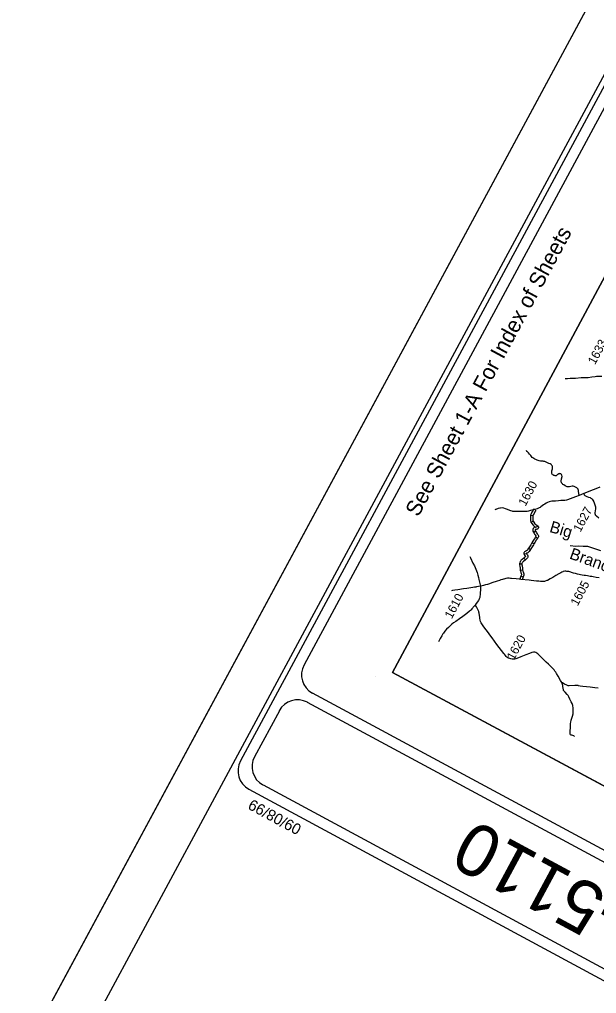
# Model space of a CAD drawing. Extents: x 1376167 to 1379209, y 761324 to 763997.
# Drawn here: x 1376166.9 to 1376443.7, y 762547.7 to 763014.5 of the extents above; entities that cross this region are included whole.
import ezdxf

# ---------------------------------------------------------------- set-up
doc = ezdxf.new("R2010")
doc.units = 0
for name, color, linetype in [('Default', 7, 'Continuous'), ('Old_Level_1', 7, 'Continuous'), ('Sheet Border Standard 30in CELL', 7, 'Continuous'), ('Sheet Cutting Line CELL', 7, 'Continuous'), ('Sheet Plot Border Inside CELL', 7, 'Continuous'), ('Sheet Plot Border Outside CELL', 7, 'Continuous'), ('Sheet Title CELL', 7, 'Continuous')]:
    doc.layers.add(name, color=color, linetype=linetype)

msp = doc.modelspace()

# ---------------------------------------------------------------- linework, layer by layer
at = {"layer": 'Default'}
for p, q in [((1376437.56, 762787.25), (1376435.36, 762786.42)), ((1376415.13, 762779.97), (1376414.13, 762779.68)), ((1376412.06, 762776.99), (1376413.16, 762776.71)), ((1376412.2, 762773.65), (1376413.22, 762774.14)), ((1376413.43, 762768.72), (1376414.4, 762769.29)), ((1376414.35, 762771.2), (1376415.72, 762771.59)), ((1376414.47, 762766.52), (1376415.41, 762765.92)), ((1376411.03, 762761.1), (1376411.98, 762760.49)), ((1376412.74, 762763.79), (1376413.69, 762763.19)), ((1376408.8, 762756.33), (1376409.53, 762755.48)), ((1376408.82, 762758.44), (1376409.97, 762758.55)), ((1376406.74, 762753.66), (1376407.88, 762753.61)), ((1376407.1, 762750.44), (1376408.21, 762750.68)), ((1376407.42, 762747.71), (1376408.48, 762747.33))]:
    msp.add_line(p, q, dxfattribs=at)
for points in [[(1376428.65, 762842.47), (1376429.73, 762842.51), (1376431.08, 762842.55), (1376432.73, 762842.67), (1376433.63, 762842.64), (1376436.24, 762842.87), (1376437.65, 762842.9), (1376439.73, 762842.96), (1376441.45, 762843.2), (1376442.95, 762843.46), (1376443.59, 762843.53), (1376444.38, 762843.56), (1376445.29, 762843.61), (1376446.28, 762843.59)], [(1376422.31, 762796.97), (1376422.22, 762797.4), (1376422.18, 762797.8), (1376422.23, 762798.12), (1376422.4, 762798.64), (1376422.56, 762799.07), (1376422.6, 762799.25), (1376422.63, 762799.59), (1376422.61, 762800), (1376422.49, 762800.42), (1376422.28, 762800.81), (1376422.11, 762801.03), (1376421.88, 762801.23), (1376421.44, 762801.49), (1376420.84, 762801.75), (1376420.22, 762802.03), (1376419.77, 762802.21), (1376418.81, 762802.6), (1376418.4, 762802.74), (1376418.14, 762802.82), (1376417.96, 762802.8), (1376417.37, 762802.76), (1376417.05, 762802.77), (1376416.72, 762802.82), (1376416.1, 762803.02), (1376415.24, 762803.38), (1376414.92, 762803.51), (1376414.12, 762803.81), (1376413.54, 762804.07), (1376413.08, 762804.39), (1376412.86, 762804.61), (1376412.53, 762805.05), (1376412.13, 762805.52), (1376411.58, 762806.16), (1376410.97, 762806.84), (1376410.51, 762807.27), (1376410.32, 762807.5), (1376410.09, 762807.86)], [(1376435.36, 762786.42), (1376435.05, 762788.41), (1376434.98, 762788.79), (1376434.89, 762789.18), (1376434.81, 762789.44), (1376434.55, 762789.79), (1376434.26, 762790.01), (1376433.87, 762790.25), (1376433.28, 762790.59), (1376432.88, 762790.75), (1376432.52, 762790.83), (1376432.22, 762790.81), (1376431.98, 762790.79), (1376430.71, 762790.6), (1376430.22, 762790.49), (1376429.53, 762790.56), (1376429.3, 762790.64), (1376428.69, 762790.99), (1376427.93, 762791.4), (1376427.53, 762791.69), (1376427.27, 762792.01), (1376426.94, 762792.45), (1376426.86, 762792.64), (1376426.75, 762792.88), (1376426.72, 762793.2), (1376426.91, 762794.32), (1376427.11, 762795.53), (1376427.01, 762796.15), (1376426.84, 762796.48), (1376426.61, 762796.7), (1376426.37, 762796.8), (1376426.13, 762796.85), (1376425.9, 762796.83), (1376425.62, 762796.76), (1376425.12, 762796.48), (1376424.83, 762796.28), (1376424.51, 762795.91), (1376424.3, 762795.78), (1376424.09, 762795.76), (1376423.88, 762795.81), (1376423.57, 762795.88), (1376423.34, 762795.92), (1376423.11, 762796.01), (1376422.69, 762796.22), (1376422.58, 762796.34), (1376422.41, 762796.57), (1376422.31, 762796.97)], [(1376445.31, 762790.3), (1376443.4, 762789.59), (1376442.12, 762789.08), (1376441.58, 762788.85), (1376439.64, 762788.09), (1376437.56, 762787.25)], [(1376435.36, 762786.42), (1376433.53, 762785.74), (1376429.79, 762784.21), (1376429.26, 762784.1), (1376428.51, 762784.03), (1376427.45, 762783.98), (1376426.54, 762783.9), (1376425.42, 762783.79), (1376424.01, 762783.7), (1376423.26, 762783.67), (1376422.6, 762783.62), (1376422.25, 762783.58), (1376421.02, 762783.3), (1376420.2, 762783.02), (1376419.45, 762782.63), (1376418.83, 762782.28), (1376418.26, 762781.89), (1376417.61, 762781.4), (1376417.01, 762780.97), (1376416.66, 762780.69), (1376416.12, 762780.38), (1376415.13, 762779.97)], [(1376437.56, 762787.25), (1376437.81, 762786.74), (1376438.09, 762786.44), (1376438.43, 762786.26), (1376439.07, 762785.95), (1376439.87, 762785.58), (1376440.55, 762785.39), (1376440.99, 762785.15), (1376441.3, 762784.93), (1376441.61, 762784.59), (1376441.93, 762784.12), (1376442.34, 762783.3), (1376443.04, 762781.43), (1376443.12, 762780.9), (1376443.17, 762780.52), (1376443.16, 762779.96), (1376443.03, 762779.01), (1376442.9, 762778.01), (1376442.87, 762777.65), (1376442.97, 762777.37), (1376443.09, 762777.12), (1376443.33, 762776.84), (1376443.62, 762776.57), (1376444.84, 762775.72)], [(1376409.99, 762778.75), (1376409.31, 762778.65), (1376408.82, 762778.67), (1376407.7, 762778.67), (1376406.5, 762778.68), (1376405.84, 762778.67), (1376405.3, 762778.7), (1376404.13, 762778.67), (1376403.48, 762778.77), (1376403.19, 762778.83), (1376402.56, 762779.07), (1376400.53, 762779.84), (1376399.97, 762780.02), (1376399.23, 762780.22), (1376398.4, 762780.38), (1376397.57, 762780.37), (1376397.27, 762780.3), (1376396.5, 762780.08), (1376395.43, 762779.7), (1376395.14, 762779.59), (1376394.85, 762779.44)], [(1376413.64, 762779.95), (1376413.3, 762779.35), (1376412.7, 762778.36), (1376412.28, 762777.55), (1376412.06, 762776.99), (1376411.97, 762776.36), (1376411.97, 762775.58), (1376411.95, 762774.93), (1376411.96, 762774.33), (1376412.2, 762773.65), (1376412.67, 762772.89), (1376413.29, 762772.11), (1376413.77, 762771.65), (1376414.35, 762771.2), (1376414.03, 762771.13), (1376413.69, 762771.01), (1376413.43, 762770.76), (1376413.23, 762770.47), (1376413.09, 762770.13), (1376413.07, 762769.65), (1376413.09, 762769.54), (1376413.17, 762769.22), (1376413.43, 762768.72), (1376413.72, 762768.27), (1376413.96, 762767.86), (1376414.26, 762767.45), (1376414.48, 762767.07), (1376414.62, 762766.79), (1376414.55, 762766.64), (1376414.47, 762766.52), (1376414.17, 762766.04), (1376413.82, 762765.49), (1376413.19, 762764.46), (1376412.87, 762763.97), (1376412.44, 762763.31), (1376412.12, 762762.76), (1376411.52, 762761.83), (1376410.73, 762760.62), (1376410.49, 762760.24), (1376410.2, 762759.93), (1376410.12, 762759.89), (1376409.96, 762759.8), (1376409.67, 762759.68), (1376409.4, 762759.54), (1376409.18, 762759.37), (1376408.97, 762759.12), (1376408.87, 762758.81), (1376408.82, 762758.44), (1376408.91, 762758.07), (1376409.18, 762757.71), (1376409.49, 762757.36), (1376409.56, 762757.28), (1376409.61, 762757.16), (1376409.61, 762757.15), (1376409.6, 762757.12), (1376409.48, 762757), (1376409.16, 762756.66), (1376408.8, 762756.33), (1376407.98, 762755.66), (1376407.56, 762755.3), (1376407.3, 762755.01), (1376407.05, 762754.69), (1376406.82, 762754.14), (1376406.74, 762753.66), (1376406.79, 762753.07), (1376406.87, 762752.44), (1376406.95, 762752.1), (1376406.98, 762751.96), (1376407, 762751.42), (1376407.1, 762750.44), (1376407.32, 762749.77), (1376407.42, 762749.5), (1376407.55, 762748.99), (1376407.63, 762748.71), (1376407.63, 762748.44), (1376407.64, 762748.36), (1376407.42, 762747.71), (1376406.88, 762746.33)], [(1376414.62, 762779.41), (1376414.27, 762778.78), (1376413.68, 762777.81), (1376413.31, 762777.09), (1376413.16, 762776.71), (1376413.1, 762776.28), (1376413.1, 762775.56), (1376413.08, 762774.91), (1376413.08, 762774.53), (1376413.22, 762774.14), (1376413.59, 762773.54), (1376414.13, 762772.86), (1376414.51, 762772.5), (1376415.03, 762772.09), (1376415.72, 762771.59), (1376415.77, 762771.25), (1376415.8, 762770.98), (1376415.64, 762770.5), (1376415.28, 762770.27), (1376415.03, 762770.19), (1376414.68, 762770.12), (1376414.34, 762770.04), (1376414.29, 762770.03), (1376414.23, 762769.94), (1376414.21, 762769.88), (1376414.2, 762769.76), (1376414.23, 762769.62), (1376414.4, 762769.29), (1376414.68, 762768.86), (1376414.9, 762768.48), (1376415.2, 762768.07), (1376415.47, 762767.6), (1376415.78, 762766.96), (1376415.77, 762766.56), (1376415.62, 762766.29), (1376415.53, 762766.08), (1376415.41, 762765.92), (1376415.12, 762765.44), (1376414.77, 762764.89), (1376414.14, 762763.87), (1376413.82, 762763.35), (1376413.39, 762762.72), (1376413.08, 762762.18), (1376412.47, 762761.22), (1376411.68, 762760.02), (1376411.38, 762759.54), (1376410.91, 762759.06), (1376410.69, 762758.91), (1376410.45, 762758.78), (1376410.15, 762758.66), (1376410.01, 762758.58), (1376409.97, 762758.55), (1376409.97, 762758.54), (1376410.05, 762758.43), (1376410.35, 762758.09), (1376410.53, 762757.87), (1376410.71, 762757.46), (1376410.75, 762757.09), (1376410.68, 762756.78), (1376410.53, 762756.46), (1376410.28, 762756.22), (1376409.95, 762755.86), (1376409.53, 762755.48), (1376408.7, 762754.8), (1376408.36, 762754.5), (1376408.17, 762754.29), (1376408.02, 762754.11), (1376407.91, 762753.84), (1376407.88, 762753.61), (1376407.91, 762753.19), (1376407.98, 762752.64), (1376408.06, 762752.32), (1376408.1, 762752.08), (1376408.12, 762751.5), (1376408.21, 762750.68), (1376408.39, 762750.14), (1376408.5, 762749.84), (1376408.63, 762749.29), (1376408.76, 762748.88), (1376408.76, 762748.45), (1376408.76, 762748.19), (1376408.48, 762747.33), (1376407.93, 762745.92)], [(1376414.13, 762779.68), (1376412.65, 762779.26), (1376411.96, 762779.1), (1376411.05, 762778.85), (1376410.41, 762778.75), (1376409.99, 762778.75)], [(1376445.76, 762759.78), (1376439.49, 762761.92), (1376437.21, 762761.91), (1376434.8, 762762.02), (1376433.67, 762761.93), (1376430.95, 762762.28)], [(1376382.87, 762757.09), (1376383.21, 762756.46), (1376384.32, 762754.01), (1376385.16, 762752.58), (1376385.83, 762751.07), (1376386.17, 762750.27), (1376386.42, 762749.51), (1376386.79, 762748.19), (1376387.04, 762747.09), (1376387.24, 762746.06), (1376387.72, 762744.26), (1376387.96, 762742.89)], [(1376407.4, 762746.12), (1376406.55, 762746.2), (1376405.14, 762746.42), (1376402.94, 762746.58), (1376402.37, 762746.64), (1376401.71, 762746.67), (1376401.02, 762746.67), (1376400.38, 762746.63), (1376400.15, 762746.56), (1376399.74, 762746.46), (1376399.19, 762746.32), (1376399.03, 762746.28), (1376398.51, 762746.15), (1376397.77, 762745.88), (1376397.11, 762745.66), (1376395.99, 762745.32), (1376393.52, 762744.5), (1376392.27, 762744.08), (1376391.32, 762743.76), (1376390.4, 762743.49), (1376389.54, 762743.22), (1376388.82, 762743.02), (1376387.96, 762742.89)], [(1376444.89, 762746.96), (1376443.56, 762747.14), (1376442.11, 762747.35), (1376441.41, 762747.49), (1376440.6, 762747.6), (1376439.39, 762747.8), (1376438.3, 762748), (1376437.75, 762748.08), (1376436.82, 762748.2), (1376436.02, 762748.36), (1376435.33, 762748.47), (1376434.53, 762748.69), (1376433.54, 762748.94), (1376432.55, 762749.21), (1376430.38, 762749.94), (1376429.47, 762750.01), (1376428.96, 762750.06), (1376428.51, 762750.05), (1376427.71, 762749.9), (1376427.44, 762749.8), (1376427.01, 762749.64), (1376426.51, 762749.34), (1376425.57, 762748.79), (1376424.15, 762747.99), (1376422.66, 762747.11), (1376421.38, 762746.37), (1376420.12, 762745.66), (1376419.8, 762745.56), (1376419.04, 762745.25), (1376418.7, 762745.18), (1376418.29, 762745.14), (1376417.49, 762745.12), (1376416.75, 762745.19), (1376415.94, 762745.24), (1376414.91, 762745.35), (1376413.65, 762745.48), (1376412.35, 762745.6), (1376411.3, 762745.72), (1376407.4, 762746.12)], [(1376387.96, 762742.89), (1376387.05, 762742.75), (1376386.05, 762742.57), (1376385.71, 762742.5), (1376385.22, 762742.41), (1376384.27, 762742.29), (1376381.39, 762741.81), (1376379.89, 762741.61), (1376377.22, 762741.19), (1376375.73, 762740.98), (1376374.64, 762740.82), (1376374.1, 762740.73)], [(1376387.96, 762742.89), (1376387.99, 762741.2), (1376387.91, 762739.74), (1376387.83, 762738.85), (1376387.73, 762738.02), (1376387.64, 762737.5), (1376387.55, 762737.16), (1376387.39, 762736.78), (1376387.2, 762736.37), (1376387.04, 762736.11), (1376386.35, 762735.18), (1376386.1, 762734.82), (1376385.91, 762734.6), (1376385.4, 762733.87)], [(1376385.4, 762733.87), (1376384.87, 762733.22), (1376384.58, 762732.83), (1376384.31, 762732.47), (1376383.9, 762732.03), (1376383.52, 762731.6), (1376383.19, 762731.25), (1376382.8, 762730.86), (1376381.52, 762729.83), (1376379.48, 762728.33), (1376378.02, 762727.28), (1376376.19, 762726.04), (1376375.15, 762725.31), (1376374.29, 762724.66), (1376373.76, 762724.2), (1376373.3, 762723.73), (1376372.61, 762723.04), (1376371.79, 762722.24), (1376370.93, 762721.28), (1376370.23, 762720.31), (1376370.03, 762720.02), (1376369.44, 762719.15), (1376368.66, 762717.83), (1376368.3, 762717.19), (1376368, 762716.61), (1376367.82, 762716.17)], [(1376400.32, 762709.21), (1376399.97, 762709.61), (1376399.49, 762710.24), (1376399.19, 762710.61), (1376395.92, 762714.99), (1376393.55, 762718.15), (1376392.95, 762718.97), (1376392.15, 762720.09), (1376391.31, 762721.23), (1376390.69, 762722.05), (1376389.65, 762723.37), (1376388.94, 762724.34), (1376388.59, 762724.83), (1376388.35, 762725.31), (1376388.08, 762725.92), (1376387.83, 762726.69), (1376387.7, 762727.55), (1376387.68, 762727.85), (1376387.38, 762729.98), (1376387.28, 762730.4), (1376387.2, 762730.75), (1376387.03, 762731.12), (1376386.46, 762732.3), (1376386.08, 762732.97), (1376385.62, 762733.61), (1376385.4, 762733.87)], [(1376427.05, 762696.66), (1376426.44, 762697.63), (1376425.22, 762699.76), (1376424.51, 762701.02), (1376424.09, 762701.71), (1376423.72, 762702.21), (1376423.3, 762702.81), (1376421.48, 762704.7), (1376420.66, 762705.48), (1376419.55, 762706.56), (1376417.94, 762708.11), (1376416.99, 762709.03), (1376415.45, 762710.51), (1376414.98, 762710.85), (1376414.59, 762711.06), (1376414.04, 762711.22), (1376413.69, 762711.26), (1376413.41, 762711.24), (1376412.65, 762711.06), (1376411.57, 762710.66), (1376409.81, 762709.92), (1376407.38, 762709), (1376406.24, 762708.55), (1376405.01, 762708.13), (1376404.37, 762707.95), (1376403.84, 762707.91), (1376403.19, 762707.93), (1376402.61, 762708.03), (1376402.01, 762708.19), (1376401.41, 762708.46), (1376400.73, 762708.86), (1376400.32, 762709.21)], [(1376444.38, 762693.98), (1376442.88, 762694.11), (1376441.79, 762694.33), (1376440.61, 762694.56), (1376437.02, 762694.86), (1376435.85, 762695.02), (1376435.04, 762695.17), (1376434.81, 762695.24), (1376434.13, 762695.33), (1376433.34, 762695.32), (1376430.49, 762695.16), (1376430.04, 762695.21), (1376429.71, 762695.29), (1376429.4, 762695.42), (1376428.31, 762695.99), (1376427.39, 762696.52), (1376427.05, 762696.66)], [(1376433.09, 762670.92), (1376432.76, 762671.17), (1376432.32, 762671.4), (1376431.86, 762671.46), (1376431.68, 762671.51), (1376431.46, 762671.56), (1376431.21, 762671.72), (1376431.08, 762671.93), (1376431.04, 762672.24), (1376431.07, 762673.35), (1376431.15, 762675.18), (1376431.19, 762676.39), (1376431.21, 762677.11), (1376431.28, 762677.69), (1376431.52, 762678.69), (1376431.68, 762679.17), (1376432.1, 762680.55), (1376432.39, 762681.7), (1376432.44, 762682.38), (1376432.43, 762683.68), (1376432.42, 762684.75), (1376432.37, 762685.43), (1376432.31, 762685.75), (1376432.15, 762686.2), (1376431.96, 762686.71), (1376431.56, 762687.49), (1376430.93, 762688.68), (1376430.41, 762689.81), (1376430.03, 762690.5), (1376429.65, 762691), (1376428.6, 762692.1), (1376428.15, 762692.59), (1376427.9, 762692.94), (1376427.8, 762693.24), (1376427.67, 762694.03), (1376427.56, 762694.83), (1376427.45, 762695.38), (1376427.05, 762696.66)]]:
    msp.add_lwpolyline(points, dxfattribs=at)
at = {"layer": 'Old_Level_1'}
for points in [[(1376622.61, 762553.05), (1376345.79, 762701.47), (1376550.88, 763083.99), (1376827.7, 762935.57)], [(1376345.79, 762701.47), (1376660.36, 762532.81), (1376865.45, 762915.33), (1376550.88, 763083.99)]]:
    msp.add_lwpolyline(points, close=True, dxfattribs=at)
at = {"layer": 'Sheet Border Standard 30in CELL'}
msp.add_line((1376337.75, 762699.38), (1376337.75, 762699.38), dxfattribs=at)
at = {"layer": 'Sheet Cutting Line CELL'}
msp.add_line((1376166.94, 762515.18), (1376966.07, 763997.49), dxfattribs=at)
at = {"layer": 'Sheet Plot Border Inside CELL'}
msp.add_lwpolyline([(1377121.6, 762015.28), (1377912.43, 763482.18), (1376983.7, 763982.88), (1376192.87, 762515.97)], close=True, dxfattribs=at)
at = {"layer": 'Sheet Plot Border Outside CELL'}
msp.add_lwpolyline([(1376966.07, 763997.49), (1376166.94, 762515.18), (1377135.18, 761993.19), (1377934.31, 763475.5)], close=True, dxfattribs=at)
at = {"layer": 'Sheet Title CELL'}
for p, q in [((1377042.48, 762295.37), (1376307.48, 762691.62)), ((1377202.95, 762203.18), (1376305.11, 762687.22))]:
    msp.add_line(p, q, dxfattribs=at)
for points in [[(1376975.27, 763961.87), (1376272.92, 762659.12)], [(1376977.29, 763955.09), (1376303.44, 762705.17)], [(1376291.57, 762683.15), (1376279.7, 762661.15)], [(1376283.76, 762647.62), (1377181.59, 762163.57)], [(1376276.98, 762645.58), (1377183.62, 762156.8)], [(1376276.98, 762645.58), (1377183.62, 762156.8)]]:
    msp.add_lwpolyline(points, dxfattribs=at)
for centre, start, end in [((1376312.19, 762700.45), 151.6702, 241.6702), ((1376300.33, 762678.44), 61.6702, 151.6702), ((1376281.69, 762654.41), 151.6702, 241.6702), ((1376288.46, 762656.43), 151.6702, 241.6702)]:
    msp.add_arc(centre, 10, start, end, dxfattribs=at)

# ---------------------------------------------------------------- texts
at = {"layer": 'Default'}
for s, rotation, p in [('Big', 343.4163, (1376420.76, 762768.99)), ('Branch', 340.1164, (1376430.32, 762756.25))]:
    msp.add_text(s, height=5.58, rotation=rotation, dxfattribs=at).set_placement(p)
at = {"layer": 'Old_Level_1'}
for s, p in [('1633', (1376442.92, 762848.77)), ('1630', (1376409.59, 762780.92)), ('1627', (1376435.92, 762768.5)), ('1605', (1376434.6, 762733.11)), ('1610', (1376374.22, 762726.95)), ('1620', (1376404.05, 762707.12))]:
    msp.add_text(s, height=4.185, rotation=61.8015, dxfattribs=at).set_placement(p)
at = {"layer": 'Sheet Title CELL'}
for s, height, rotation, p in [('See Sheet 1-A For Index of Sheets', 7.5, 61.6702, (1376358.18, 762775.73)), ('09/08/99', 5.25, 151.6702, (1376302.62, 762628.07)), ('B-5110  ', 25, 151.6702, (1376479.23, 762580.41))]:
    msp.add_text(s, height=height, rotation=rotation, dxfattribs=at).set_placement(p)

doc.saveas('drawing.dxf')
